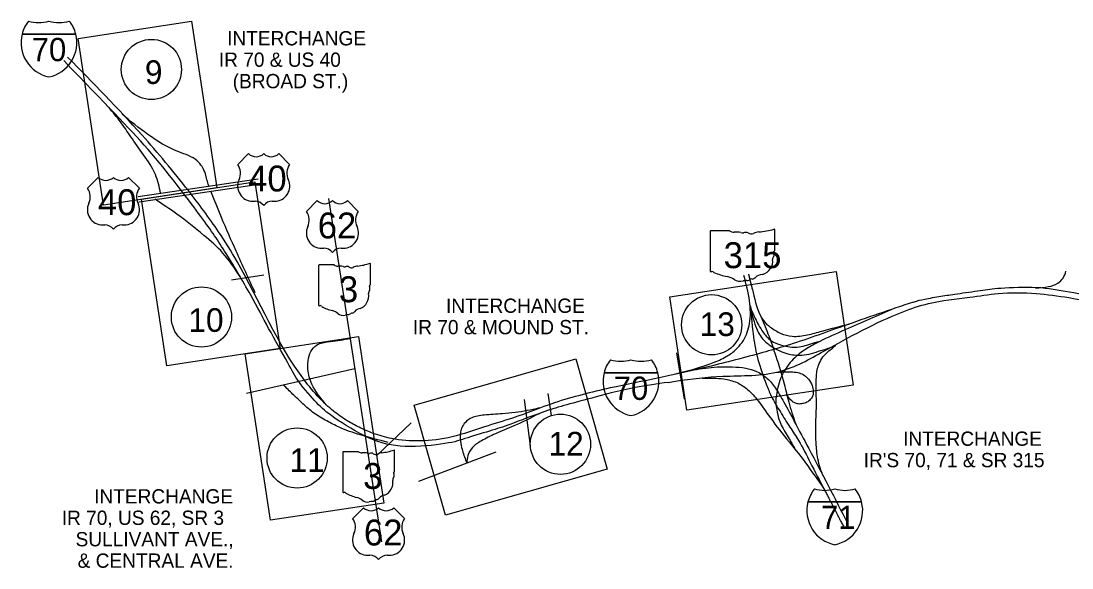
# Model space of a CAD drawing. Extents: x -13 to 322, y -402 to 112.
# Drawn here: x -4.06 to 3.22, y 66.9 to 70.69 of the extents above; entities that cross this region are included whole.
import ezdxf

# ---------------------------------------------------------------- set-up
doc = ezdxf.new("R2010")
doc.units = 0
for name, color, linetype in [('Default', 7, 'Continuous'), ('GM_X_Interstate_Shield', 7, 'Continuous'), ('GM_X_State_Shield', 7, 'Continuous'), ('GM_X_US_Shield', 7, 'Continuous'), ('SH_Data', 7, 'Continuous'), ('SH_Text', 7, 'Continuous')]:
    doc.layers.add(name, color=color, linetype=linetype)

# ---------------------------------------------------------------- blocks, each defined once
blk = doc.blocks.new('FENCE')
at = {"layer": 'Default'}
blk.add_lwpolyline([(-54.6, 79.5), (232.4, 79.5), (232.4, -116), (-54.6, -116)], close=True, dxfattribs=at)

msp = doc.modelspace()

# ---------------------------------------------------------------- linework, layer by layer
at = {"layer": 'GM_X_Interstate_Shield'}
for p, q in [((-4.0536, 70.5971), (-3.6816, 70.5971)), ((-3.6816, 70.5971), (-4.0536, 70.5971)), ((-3.6816, 70.5971), (-4.0536, 70.5971)), ((-0.0218, 68.253), (0.3502, 68.253)), ((0.3502, 68.253), (-0.0218, 68.253)), ((0.3502, 68.253), (-0.0218, 68.253)), ((1.3901, 67.3593), (1.7621, 67.3593)), ((1.7621, 67.3593), (1.3901, 67.3593)), ((1.7621, 67.3593), (1.3901, 67.3593))]:
    msp.add_line(p, q, dxfattribs=at)
for centre, start, end in [((-3.8193, 70.5378), 141.66896, 165.80665), ((-3.9382, 70.9189), 253.00908, 286.99093), ((-3.797, 70.9189), 253.00908, 286.99093), ((-3.916, 70.5378), 14.19335, 38.33104), ((-3.8193, 70.5378), 165.80665, 258.46304), ((-3.916, 70.5378), 281.53696, 14.19335), ((0.2125, 68.1937), 141.66896, 165.80665), ((0.0936, 68.5748), 253.00908, 286.99093), ((0.2348, 68.5748), 253.00908, 286.99093), ((0.1158, 68.1937), 14.19335, 38.33104), ((0.2125, 68.1937), 165.80665, 258.46304), ((0.1158, 68.1937), 281.53696, 14.19335), ((1.6245, 67.3), 141.66896, 165.80665), ((1.5055, 67.6811), 253.00908, 286.99093), ((1.6468, 67.6811), 253.00908, 286.99093), ((1.5278, 67.3), 14.19335, 38.33104), ((1.6245, 67.3), 165.80665, 258.46304), ((1.5278, 67.3), 281.53696, 14.19335)]:
    msp.add_arc(centre, 0.2417, start, end, dxfattribs=at)
at = {"layer": 'GM_X_State_Shield'}
for p, q in [((0.8478, 69.2353), (0.7164, 69.2353)), ((1.1607, 69.0996), (1.1607, 69.2421)), ((0.712, 69.2307), (0.712, 68.9582)), ((1.1607, 69.0996), (1.1607, 69.0996)), ((-1.9997, 68.9949), (-1.9997, 68.7224)), ((-1.891, 68.9996), (-1.9962, 68.9996)), ((-1.6407, 68.8638), (-1.6407, 69.0063)), ((-1.6408, 68.8638), (-1.6407, 68.8638)), ((-1.7233, 67.7072), (-1.8284, 67.7072)), ((-1.473, 67.5715), (-1.473, 67.714)), ((-1.832, 67.7025), (-1.832, 67.4301)), ((-1.4731, 67.5715), (-1.473, 67.5715))]:
    msp.add_line(p, q, dxfattribs=at)
for centre, radius, start, end in [((-1.9956, 68.9954), 0.00416, 98.1301, 188.1301), ((-1.866, 69.0312), 0.0403, 231.61951, 271.11188), ((-1.8526, 68.8466), 0.1448, 80.48669, 94.98827), ((-1.8198, 68.9969), 0.0116, 219.79206, 297.10237), ((-1.8027, 68.9654), 0.0242, 54.46668, 119.14113), ((-1.7714, 69.0086), 0.0291, 233.85621, 294.82819), ((-1.72, 68.9163), 0.0766, 97.34618, 120.76885), ((-1.7686, 69.371), 0.3807, 275.84447, 288.90645), ((-1.6447, 69.0069), 0.004, 351.86209, 97.738), ((-1.7473, 68.786), 0.0952, 292.30889, 8.98584), ((-1.6264, 68.8041), 0.027, 136.8065, 186.92959), ((-1.6417, 68.8533), 0.00618, 107.94398, 210.33697), ((-1.681, 68.8353), 0.0371, 340.03296, 23.64957), ((-1.645, 68.8632), 0.00428, 289.60381, 7.73413), ((-1.9955, 68.7218), 0.0042, 171.95839, 258.30661), ((-1.9949, 68.7497), 0.032, 267.33899, 280.60386), ((-1.9884, 68.7067), 0.0115, 29.74838, 93.27175), ((-1.8426, 68.9515), 0.2749, 240.41292, 257.1985), ((-1.9246, 68.6), 0.086, 47.18416, 75.83597), ((-1.8315, 68.7054), 0.0546, 230.70037, 286.29184), ((-1.8, 68.6112), 0.0448, 85.69512, 111.20995), ((-1.796, 68.685), 0.0291, 268.77702, 315.54927), ((-1.7697, 68.6586), 0.00819, 65.75173, 132.64842), ((-1.7732, 68.696), 0.0308, 282.87319, 323.27711), ((-1.7071, 68.6459), 0.0521, 94.40312, 142.57675), ((-1.8279, 67.7031), 0.00416, 98.1301, 188.1301), ((-1.6983, 67.7389), 0.0403, 231.61951, 271.11188), ((-1.6009, 68.0787), 0.3807, 275.84447, 288.90645), ((-1.477, 67.7146), 0.004, 351.86209, 97.738), ((-1.6849, 67.5543), 0.1448, 80.48669, 94.98827), ((-1.652, 67.7045), 0.0116, 219.79206, 297.10237), ((-1.635, 67.673), 0.0242, 54.46668, 119.14113), ((-1.6037, 67.7162), 0.0291, 233.85621, 294.82819), ((-1.5523, 67.624), 0.0766, 97.34618, 120.76885), ((-1.4739, 67.561), 0.00618, 107.94398, 210.33697), ((-1.4773, 67.5709), 0.00428, 289.60381, 7.73413), ((-1.5796, 67.4937), 0.0952, 292.30889, 8.98584), ((-1.4587, 67.5118), 0.027, 136.8065, 186.92959), ((-1.5133, 67.543), 0.0371, 340.03296, 23.64957), ((-1.8278, 67.4295), 0.0042, 171.95839, 258.30661), ((-1.8272, 67.4574), 0.032, 267.33899, 280.60386), ((-1.8206, 67.4144), 0.0115, 29.74838, 93.27175), ((-1.6749, 67.6592), 0.2749, 240.41292, 257.1985), ((-1.7568, 67.3077), 0.086, 47.18416, 75.83597), ((-1.6638, 67.413), 0.0546, 230.70037, 286.29184), ((-1.6323, 67.3188), 0.0448, 85.69512, 111.20995), ((-1.6283, 67.3926), 0.0291, 268.77702, 315.54927), ((-1.602, 67.3662), 0.00819, 65.75173, 132.64842), ((-1.6055, 67.4037), 0.0308, 282.87319, 323.27711), ((-1.5394, 67.3536), 0.0521, 94.40312, 142.57675)]:
    msp.add_arc(centre, radius, start, end, dxfattribs=at)
for centre, major_axis, start_param, end_param in [((0.7172, 69.2312), (0.0052, 0), 1.712693, 3.28349), ((0.8791, 69.267), (0.0504, 0), 4.042523, 4.731795), ((1.0009, 69.6068), (0.4758, 0), 4.814394, 5.042369), ((1.1557, 69.2427), (0.005, 0), 6.141152, 7.989035), ((0.8958, 69.0824), (0.181, 0), 1.404758, 1.657858), ((0.9369, 69.2326), (0.0145, 0), 3.836095, 5.185415), ((0.9583, 69.2012), (0.0302, 0), 0.950623, 2.079405), ((0.9973, 69.2443), (0.0364, 0), 4.081561, 5.145723), ((1.0616, 69.1521), (0.0957, 0), 1.699011, 2.107814), ((1.1596, 69.0891), (0.00773, 0), 1.883978, 3.671073), ((1.1554, 69.099), (0.00535, 0), 5.05454, 6.418171), ((1.0275, 69.0218), (0.119, 0), 5.101752, 6.440018), ((1.1786, 69.0399), (0.0338, 0), 2.387724, 3.262537), ((1.1104, 69.0711), (0.0464, 0), 5.934695, 6.695948), ((0.7172, 68.9576), (0.00524, 0), 3.00124, 4.508301), ((0.718, 68.9855), (0.04, 0), 4.665946, 4.897461), ((0.7262, 68.9425), (0.0144, 0), 0.519207, 1.627899), ((0.9084, 69.1873), (0.3436, 0), 4.195997, 4.488961), ((0.8059, 68.8358), (0.1075, 0), 0.823519, 1.323587), ((0.9222, 68.9411), (0.0682, 0), 4.026481, 4.996735), ((0.9616, 68.8469), (0.0561, 0), 1.495662, 1.94098), ((0.9666, 68.9207), (0.0363, 0), 4.691044, 5.507374), ((0.9995, 68.8944), (0.0102, 0), 1.147584, 2.315152), ((0.9951, 68.9318), (0.0385, 0), 4.937069, 5.64225), ((1.0777, 68.8817), (0.0652, 0), 1.647645, 2.488434)]:
    msp.add_ellipse(centre, major_axis=major_axis, ratio=0.8, start_param=start_param, end_param=end_param, dxfattribs=at)
at = {"layer": 'GM_X_US_Shield'}
for p, q in [((-2.4847, 69.7699), (-2.5595, 69.6951)), ((-2.2005, 69.6951), (-2.2753, 69.7699)), ((-3.5255, 69.606), (-3.6003, 69.5312)), ((-3.2413, 69.5312), (-3.3161, 69.606)), ((-2.4548, 69.4408), (-2.4398, 69.4408)), ((-2.3202, 69.4408), (-2.3052, 69.4408)), ((-2.0087, 69.4447), (-2.0835, 69.3699)), ((-1.7245, 69.3699), (-1.7993, 69.4447)), ((-3.4956, 69.2769), (-3.4806, 69.2769)), ((-3.361, 69.2769), (-3.346, 69.2769)), ((-1.9788, 69.1157), (-1.9638, 69.1157)), ((-1.8441, 69.1157), (-1.8292, 69.1157)), ((-1.6888, 67.3197), (-1.7636, 67.245)), ((-1.4046, 67.245), (-1.4794, 67.3197)), ((-1.6589, 66.9907), (-1.6439, 66.9907)), ((-1.5243, 66.9907), (-1.5093, 66.9907))]:
    msp.add_line(p, q, dxfattribs=at)
for centre, radius, start, end in [((-2.4323, 69.8233), 0.0748, 225.573, 314.427), ((-2.3277, 69.8233), 0.0748, 225.573, 314.427), ((-2.6452, 69.635), 0.1047, 334.54712, 35.00093), ((-2.1148, 69.635), 0.1047, 144.99907, 205.45288), ((-3.4731, 69.6594), 0.0748, 225.573, 314.427), ((-3.3684, 69.6594), 0.0748, 225.573, 314.427), ((-3.686, 69.4711), 0.1047, 334.54712, 35.00093), ((-3.1556, 69.4711), 0.1047, 144.99907, 205.45288), ((-2.456, 69.5455), 0.1047, 154.83192, 270.63826), ((-2.3041, 69.5455), 0.1047, 269.36174, 25.16808), ((-3.4967, 69.3816), 0.1047, 154.83192, 270.63826), ((-3.3448, 69.3816), 0.1047, 269.36174, 25.16808), ((-2.4398, 69.3661), 0.0748, 36.8699, 90), ((-2.3202, 69.3661), 0.0748, 90, 143.1301), ((-1.9563, 69.4981), 0.0748, 225.573, 314.427), ((-1.8516, 69.4981), 0.0748, 225.573, 314.427), ((-2.1692, 69.3099), 0.1047, 334.54712, 35.00093), ((-1.6387, 69.3099), 0.1047, 144.99907, 205.45288), ((-3.4806, 69.2021), 0.0748, 36.8699, 90), ((-3.361, 69.2021), 0.0748, 90, 143.1301), ((-1.9799, 69.2203), 0.1047, 154.83192, 270.63826), ((-1.828, 69.2203), 0.1047, 269.36174, 25.16808), ((-1.9638, 69.0409), 0.0748, 36.8699, 90), ((-1.8441, 69.0409), 0.0748, 90, 143.1301), ((-1.6365, 67.3731), 0.0748, 225.573, 314.427), ((-1.5318, 67.3731), 0.0748, 225.573, 314.427), ((-1.8494, 67.1849), 0.1047, 334.54712, 35.00093), ((-1.3189, 67.1849), 0.1047, 144.99907, 205.45288), ((-1.6601, 67.0954), 0.1047, 154.83192, 270.63826), ((-1.5082, 67.0954), 0.1047, 269.36174, 25.16808), ((-1.6439, 66.9159), 0.0748, 36.8699, 90), ((-1.5243, 66.9159), 0.0748, 90, 143.1301)]:
    msp.add_arc(centre, radius, start, end, dxfattribs=at)
at = {"layer": 'SH_Data'}
for p, q in [((-3.2487, 69.4726), (-2.4186, 69.5947)), ((-3.2436, 69.4376), (-2.4134, 69.5598)), ((-1.9303, 69.4606), (-1.5638, 67.0826)), ((-2.6041, 68.8975), (-2.378, 68.9307)), ((0.48, 68.3907), (0.5332, 68.0699)), ((-1.7485, 68.2809), (-2.4999, 68.1097)), ((-0.4116, 68.1097), (-0.3886, 67.9568)), ((-0.5747, 68.0677), (-0.533, 67.7469)), ((-1.3588, 67.9076), (-1.5956, 67.68)), ((-1.3058, 67.504), (-0.7702, 67.7061))]:
    msp.add_line(p, q, dxfattribs=at)
for points, degree in [([(0.0293, 68.1144), (-0.1759, 68.0594), (-0.3782, 68.0107), (-0.6763, 67.8934), (-0.7792, 67.86), (-0.9836, 67.7998), (-1.0876, 67.7618), (-1.4181, 67.7308), (-1.6402, 67.7803), (-1.9204, 67.9574), (-2.0027, 68.031), (-2.1485, 68.1984), (-2.1979, 68.2967), (-2.3559, 68.5758), (-2.4519, 68.7652), (-2.6662, 69.1275), (-2.7876, 69.2999), (-3.1694, 69.8087), (-3.4703, 70.1064), (-3.7638, 70.4136)], 3), ([(2.1217, 68.7431), (2.1524, 68.7533), (2.1841, 68.7617), (2.3195, 68.7847), (2.4083, 68.7979), (2.5999, 68.8247), (2.6959, 68.8403), (2.9915, 68.8527), (3.1857, 68.8151), (3.4721, 68.767), (3.5635, 68.749), (3.7498, 68.7583), (3.8458, 68.7722), (4.1303, 68.8162), (4.3223, 68.8461), (4.7428, 68.9036), (4.9712, 68.9382), (5.1993, 68.9753)], 3), ([(1.0063, 68.8308), (0.9978, 68.8659), (0.9884, 68.9003), (0.9807, 68.9351)], 2), ([(1.504, 67.4441), (1.548, 67.3596), (1.592, 67.2751), (1.6359, 67.1906)], 2)]:
    msp.add_open_spline(points, degree=degree, dxfattribs=at)
for points in [[(0.0201, 68.1485), (-0.3656, 68.0451), (-0.6563, 67.9399), (-0.8501, 67.8792), (-1.0739, 67.8102), (-1.297, 67.7814), (-1.4943, 67.7983), (-1.6209, 67.8341), (-1.7191, 67.8764), (-1.8024, 67.9217), (-1.8963, 67.9882), (-1.9948, 68.0799), (-2.0979, 68.2024), (-2.5648, 69.0244), (-2.6921, 69.2282), (-2.9015, 69.5142), (-3.2228, 69.8985), (-3.7383, 70.438)], [(-3.0941, 69.4953), (-3.1299, 69.6256), (-3.2128, 69.7625), (-3.3006, 69.8874), (-3.3718, 69.9894), (-3.4513, 70.0883)], [(-2.7596, 69.5445), (-2.7609, 69.548), (-2.7841, 69.6308), (-2.8414, 69.7207), (-2.9679, 69.7823), (-3.1835, 69.9034), (-3.3602, 70.0424)], [(-2.5438, 68.9169), (-2.6622, 69.0821), (-2.7938, 69.2041), (-2.982, 69.3522), (-3.1326, 69.454)], [(-2.4388, 68.806), (-2.5702, 69.094), (-2.6723, 69.3282), (-2.7464, 69.5108)], [(2.967, 68.8397), (3.0573, 68.8494), (3.1211, 68.8736), (3.1572, 68.9087), (3.1776, 68.9559)], [(0.4227, 68.1866), (0.4736, 68.1951), (0.8015, 68.2291), (1.1958, 68.2632), (1.5004, 68.403), (2.0434, 68.6736), (2.2244, 68.7327), (2.5111, 68.7757), (2.7075, 68.8021), (2.9708, 68.8021), (3.1973, 68.7734), (3.5452, 68.7216), (3.7165, 68.7216), (4.1393, 68.785), (4.69, 68.8605), (5.1737, 68.9343)], [(0.454, 68.242), (0.7415, 68.326), (0.8358, 68.372), (0.9014, 68.4249), (0.9428, 68.4778), (0.9853, 68.594), (0.9853, 68.7504), (0.9462, 68.9275)], [(1.0063, 68.8308), (1.0593, 68.6521), (1.0813, 68.6153), (1.1295, 68.5696), (1.2023, 68.5263), (1.2815, 68.5058), (1.3862, 68.5156), (1.4875, 68.5418), (1.6813, 68.5922)], [(2.1217, 68.7431), (1.6352, 68.5764), (1.2368, 68.4394), (1.0783, 68.3932), (0.6966, 68.2944), (0.0201, 68.1485)], [(0.9904, 68.7197), (1.0292, 68.5724), (1.0483, 68.5293), (1.0752, 68.4885), (1.1075, 68.4582), (1.135, 68.4368), (1.1962, 68.4045), (1.2499, 68.3851), (1.2951, 68.3766), (1.3646, 68.3766), (1.4305, 68.3921), (1.5628, 68.4336)], [(0.9915, 68.7084), (1.0133, 68.4998), (1.0431, 68.3462), (1.1019, 68.1742), (1.1364, 68.0918), (1.1991, 67.9825), (1.2658, 67.8758), (1.3251, 67.7844), (1.4058, 67.6324), (1.504, 67.4441)], [(1.0004, 68.6818), (1.0411, 68.5975), (1.0708, 68.5465), (1.0959, 68.5127), (1.12, 68.4884), (1.1641, 68.4596), (1.223, 68.4402), (1.2785, 68.4315), (1.3149, 68.4315), (1.4239, 68.4579), (1.4826, 68.4744)], [(1.0585, 68.6546), (1.1132, 68.523), (1.168, 68.3694), (1.2252, 68.1773), (1.2571, 68.051), (1.3039, 67.9013)], [(1.9659, 68.6897), (1.6256, 68.5408), (1.4449, 68.4562), (1.3639, 68.4088), (1.2787, 68.3368), (1.207, 68.2286), (1.1862, 68.1687), (1.1714, 68.0966), (1.1678, 68.0533), (1.1778, 67.9805), (1.1944, 67.9172), (1.2472, 67.8184), (1.296, 67.7335)], [(-1.9477, 68.0326), (-2.0464, 68.1749), (-2.0739, 68.277), (-2.0695, 68.3546), (-2.0443, 68.4141), (-2.0017, 68.4506), (-1.9185, 68.4701), (-1.7807, 68.4902)], [(1.4969, 67.5346), (1.459, 67.6566), (1.4507, 67.7157), (1.4448, 67.8126), (1.4448, 67.8874), (1.4488, 68.0495), (1.4488, 68.2256), (1.4529, 68.2627), (1.4638, 68.3056), (1.4867, 68.3523), (1.5208, 68.3907), (1.5831, 68.4437)], [(0.5974, 68.273), (0.7622, 68.2938), (0.8662, 68.2938), (0.96, 68.2853), (1.0346, 68.2626), (1.1082, 68.2142), (1.1374, 68.1845), (1.1913, 68.1054), (1.2239, 68.0508), (1.2957, 67.9166), (1.3954, 67.73), (1.6672, 67.2069)], [(0.6594, 68.2167), (0.808, 68.2105), (0.8988, 68.1853), (0.9725, 68.1376), (1.0453, 68.0585), (1.115, 67.9618), (1.3722, 67.6312), (1.504, 67.4441)], [(1.1598, 68.2564), (1.2864, 68.2595), (1.3301, 68.2523), (1.3657, 68.2354), (1.3945, 68.2094), (1.4185, 68.1657), (1.4271, 68.1243), (1.4271, 68.1107), (1.4183, 68.0842), (1.4006, 68.0624), (1.3751, 68.0463), (1.3453, 68.0383), (1.3179, 68.0383), (1.2889, 68.051), (1.2544, 68.0848), (1.2423, 68.1067)], [(-1.5182, 67.7714), (-1.7104, 67.8235), (-1.8572, 67.8765), (-1.9427, 67.9198), (-2.032, 67.9739), (-2.1081, 68.0389), (-2.1793, 68.106), (-2.243, 68.1683)], [(0.4227, 68.1866), (0.1933, 68.1513), (0.0274, 68.1141)], [(-0.4718, 68.0096), (-0.6382, 67.9775), (-0.7261, 67.9703), (-0.7902, 67.9655), (-0.8518, 67.9607), (-0.8998, 67.954), (-0.939, 67.941), (-0.975, 67.9176), (-1.0024, 67.883), (-1.017, 67.8413), (-1.0144, 67.7614), (-1.0029, 67.7136), (-0.9733, 67.6295)], [(-0.4721, 67.9703), (-0.6468, 67.8854), (-0.7751, 67.8317), (-0.8723, 67.7814), (-0.9329, 67.7371), (-0.9662, 67.6803), (-0.9737, 67.6304)]]:
    msp.add_spline(points, degree=3, dxfattribs=at)
at = {"layer": 'SH_Text'}
for centre in [(-3.1578, 70.3526), (-2.8112, 68.6392), (0.7234, 68.5856), (-0.3245, 67.7586), (-2.1486, 67.6634)]:
    msp.add_circle(centre, 0.2084, dxfattribs=at)

# ---------------------------------------------------------------- block references
for p, xscale, yscale, rotation in [((-3.2032, 69.6821), 0.004060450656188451, 0.00406045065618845, 98.65146937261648), ((-2.7642, 68.57), 0.004060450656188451, 0.00406045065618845, 98.65146937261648), ((1.4362, 68.4548), 0.004060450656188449, 0.004060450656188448, -171.42036709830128), ((-2.0474, 67.5003), 0.004060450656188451, 0.00406045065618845, 98.65146937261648), ((-0.3017, 67.8366), 0.004060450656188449, 0.004060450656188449, -164.0394165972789)]:
    msp.add_blockref('FENCE', p, dxfattribs=dict(at, xscale=xscale, yscale=yscale, rotation=rotation))

# ---------------------------------------------------------------- texts
at = {"layer": 'GM_X_Interstate_Shield'}
for s, p in [('70', (-3.9874, 70.4098)), ('70', (0.0444, 68.0656)), ('71', (1.4802, 67.172))]:
    msp.add_text(s, height=0.16115, dxfattribs=at).set_placement(p)
at = {"layer": 'GM_X_State_Shield'}
for s, height, p in [('315', 0.17948, (0.8061, 68.9774)), ('3', 0.1795, (-1.8589, 68.7416)), ('3', 0.1795, (-1.6912, 67.4493))]:
    msp.add_text(s, height=height, dxfattribs=at).set_placement(p)
at = {"layer": 'GM_X_US_Shield'}
for s, p in [('40', (-2.4878, 69.5081)), ('40', (-3.5286, 69.3442)), ('62', (-2.0056, 69.183)), ('62', (-1.6857, 67.058))]:
    msp.add_text(s, height=0.17948, dxfattribs=at).set_placement(p)
at = {"layer": 'SH_Text'}
for s, height, p in [('INTERCHANGE', 0.098862, (-2.6333, 70.5192)), ('9', 0.1636, (-3.2029, 70.2522)), ('IR 70 & US 40', 0.098862, (-2.6905, 70.3709)), ('(BROAD ST.)', 0.098862, (-2.5947, 70.2226)), ('INTERCHANGE', 0.098862, (-1.1168, 68.6681)), ('10', 0.16356, (-2.9013, 68.5366)), ('13', 0.16356, (0.6404, 68.5077)), ('IR 70 & MOUND ST.', 0.098862, (-1.346, 68.5198)), ('12', 0.16356, (-0.4068, 67.6807)), ('INTERCHANGE', 0.098862, (2.0492, 67.7479)), ('11', 0.16356, (-2.2008, 67.5669)), ("IR'S 70, 71 & SR 315", 0.098862, (1.7764, 67.5996)), ('INTERCHANGE', 0.098862, (-3.5546, 67.3487)), ('IR 70, US 62, SR 3', 0.098862, (-3.7788, 67.2004)), ('SULLIVANT AVE.,', 0.098862, (-3.683, 67.0521)), ('& CENTRAL AVE.', 0.098862, (-3.6686, 66.9038))]:
    msp.add_text(s, height=height, dxfattribs=at).set_placement(p)

doc.saveas('drawing.dxf')
